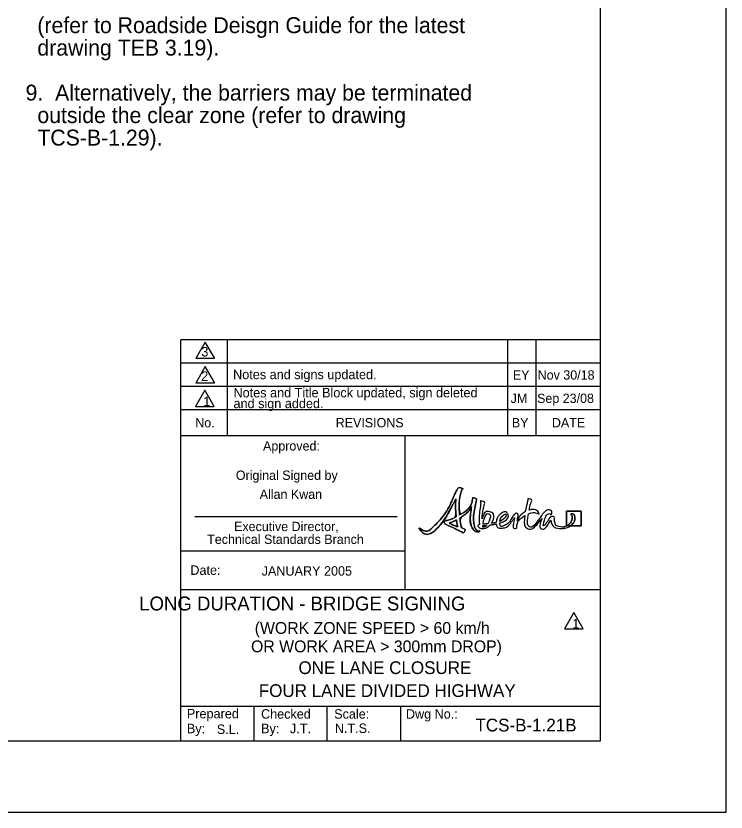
# Model space of a CAD drawing. Extents: x 2179 to 2395, y 134 to 413.
# Drawn here: x 2286.7 to 2394.7, y 133.8 to 254.8 of the extents above; entities that cross this region are included whole.
import ezdxf

# ---------------------------------------------------------------- set-up
doc = ezdxf.new("R2010")
doc.units = 0
for name, color, linetype in [('Level 1', 7, 'Continuous'), ('Level 2', 7, 'Continuous'), ('Level 20', 7, 'Continuous'), ('Level 22', 7, 'Continuous'), ('Level 44', 7, 'Continuous'), ('Level 53', 7, 'Continuous'), ('Level 60', 7, 'Continuous'), ('Level 7', 7, 'Continuous')]:
    doc.layers.add(name, color=color, linetype=linetype)

# ---------------------------------------------------------------- blocks, each defined once
blk = doc.blocks.new('REV1')
at = {"layer": 'Level 1'}
blk.add_lwpolyline([(0.114, 1.689), (-1.305, -0.781), (1.533, -0.781)], close=True, dxfattribs=at)
blk.add_text('1', height=1.448, rotation=360, dxfattribs=at).set_placement((-0.113, -0.724))

msp = doc.modelspace()

# ---------------------------------------------------------------- linework, layer by layer
at = {"layer": 'Level 1'}
for p, q in [((2375.65, 205.58), (2311.77, 205.58)), ((2375.65, 202.03), (2311.77, 202.03)), ((2375.65, 198.48), (2311.77, 198.48)), ((2375.65, 194.93), (2311.77, 194.93)), ((2311.78, 144.57), (2311.78, 191.03)), ((2311.78, 191.03), (2375.65, 191.03)), ((2345.83, 191.03), (2345.83, 167.62)), ((2311.78, 173.47), (2345.83, 173.47)), ((2311.78, 167.62), (2375.62, 167.62)), ((2311.78, 149.89), (2375.62, 149.89)), ((2322.91, 144.57), (2322.91, 149.89)), ((2334.04, 144.57), (2334.04, 149.89)), ((2345.17, 149.89), (2345.17, 144.57))]:
    msp.add_line(p, q, dxfattribs=at)
for points in [[(2394.75, 412.76), (2178.75, 412.76), (2178.75, 133.76), (2394.75, 133.76)], [(2375.62, 401.95), (2188.75, 401.95), (2188.75, 144.57), (2375.62, 144.57)], [(2315.4, 197.91), (2313.98, 195.44), (2316.82, 195.44)]]:
    msp.add_lwpolyline(points, close=True, dxfattribs=at)
at = {"layer": 'Level 2'}
msp.add_line((2345.85, 191.03), (2345.85, 191.03), dxfattribs=at)
at = {"layer": 'Level 20'}
for p, q in [((2311.78, 199.11), (2311.78, 205.58)), ((2318.87, 199.11), (2318.87, 205.58)), ((2361.46, 205.58), (2361.46, 191.03)), ((2365.77, 205.58), (2365.77, 191.03)), ((2311.78, 191.03), (2311.78, 199.11)), ((2318.87, 191.03), (2318.87, 199.11))]:
    msp.add_line(p, q, dxfattribs=at)
at = {"layer": 'Level 22'}
msp.add_line((2327.24, 144.57), (2327.24, 144.57), dxfattribs=at)
at = {"layer": 'Level 53'}
msp.add_line((2371.06, 177.31), (2370.51, 177.31), dxfattribs=at)
msp.add_lwpolyline([(2371.06, 177.31), (2372.67, 177.31), (2372.67, 179.54), (2370.44, 179.54), (2370.44, 177.31), (2370.51, 177.31)], dxfattribs=at)
for points, degree in [([(2357.07, 176.5), (2356.83, 176.53), (2356.52, 176.86), (2356.42, 177.4), (2356.25, 178.36), (2356.35, 179.32), (2356.64, 180.74), (2356.69, 181.01), (2356.87, 181.47), (2356.29, 181.56), (2356.1, 181.59), (2356.2, 181.5), (2356.15, 181.26), (2355.92, 180.2), (2355.06, 179.43), (2354.19, 178.92), (2354.1, 180.13), (2354.14, 181.48), (2354.36, 182.31), (2354.56, 183), (2354.79, 182.87), (2354.5, 183.02), (2354.2, 183.17), (2353.88, 182.97), (2353.62, 182.45), (2353.36, 181.93), (2352.17, 179.12), (2350.25, 177.22), (2349.28, 176.24), (2348.39, 176.74), (2348.21, 176.89), (2348.07, 177.02), (2348.02, 176.83), (2348.19, 176.64), (2348.99, 175.78), (2350.14, 176.27), (2350.56, 176.69), (2351.73, 177.86), (2353.08, 180.36), (2353.62, 181.42), (2353.57, 180.82), (2353.56, 179.82), (2353.67, 178.64), (2353.08, 178.36), (2352.55, 178.19), (2352.3, 178.12), (2352.02, 178.05), (2351.86, 177.94), (2351.85, 177.81), (2351.85, 177.68), (2352.03, 177.56), (2352.29, 177.43), (2352.76, 177.21), (2354.13, 176.56), (2354.47, 176.37), (2354.76, 176.2), (2354.9, 176.33), (2354.99, 176.51), (2355.1, 176.75), (2354.79, 176.88), (2354.49, 176.97), (2354.38, 177.37), (2354.29, 177.91), (2354.23, 178.5), (2354.92, 178.93), (2355.61, 179.5), (2356.01, 180.21), (2355.91, 179.62), (2355.65, 177.58), (2356.29, 176.73), (2356.43, 176.54), (2356.75, 176.33), (2357.05, 176.36), (2357.19, 176.37), (2357.27, 176.47), (2357.25, 176.5), (2357.24, 176.53), (2357.15, 176.49), (2357.07, 176.5)], 3), ([(2354.19, 178.92), (2354.1, 180.13), (2354.14, 181.48), (2354.36, 182.31), (2354.56, 183), (2354.79, 182.87), (2354.5, 183.02), (2354.2, 183.17), (2353.88, 182.97), (2353.62, 182.45), (2353.36, 181.93), (2352.17, 179.12), (2350.25, 177.22), (2349.28, 176.24), (2348.39, 176.74), (2348.21, 176.89), (2348.07, 177.02), (2348.02, 176.83), (2348.19, 176.64), (2348.99, 175.78), (2350.14, 176.27), (2350.56, 176.69), (2351.73, 177.86), (2353.08, 180.36), (2353.62, 181.42)], 3), ([(2353.62, 181.42), (2353.57, 180.82), (2353.56, 179.82), (2353.67, 178.64)], 2), ([(2357.07, 176.5), (2356.83, 176.53), (2356.52, 176.86), (2356.42, 177.4), (2356.25, 178.36), (2356.35, 179.32), (2356.64, 180.74), (2356.69, 181.01), (2356.87, 181.47), (2356.29, 181.56), (2356.1, 181.59), (2356.2, 181.5), (2356.15, 181.26), (2355.92, 180.2), (2355.06, 179.43), (2354.19, 178.92)], 3), ([(2357.61, 178.34), (2357.65, 178.91), (2357.74, 179.6), (2357.87, 180.24), (2357.93, 180.51), (2358.11, 180.98), (2357.53, 181.07), (2357.34, 181.1), (2357.37, 181.01), (2357.39, 180.76), (2357.41, 180.42), (2357.03, 178.38), (2357.23, 177.49)], 3), ([(2364.76, 179.68), (2364.83, 179.98), (2364.9, 180.28), (2364.98, 180.57), (2365.06, 180.84), (2365.28, 181.31), (2364.7, 181.4), (2364.52, 181.43), (2364.6, 181.34), (2364.54, 181.09), (2364.43, 180.63), (2364.29, 180.04), (2364.18, 179.45)], 3), ([(2354.23, 178.5), (2354.92, 178.93), (2355.61, 179.5), (2356.01, 180.21)], 2), ([(2356.01, 180.21), (2355.91, 179.62), (2355.65, 177.58), (2356.29, 176.73), (2356.43, 176.54), (2356.75, 176.33), (2357.05, 176.36), (2357.19, 176.37), (2357.27, 176.47), (2357.25, 176.5), (2357.24, 176.53), (2357.15, 176.49), (2357.07, 176.5)], 3), ([(2359.05, 177.68), (2359.46, 178.35), (2359.42, 179.26), (2358.82, 179.42), (2358.11, 179.59), (2357.76, 178.91), (2357.61, 178.34)], 3), ([(2360.27, 177.7), (2360.37, 177.73), (2360.45, 177.76), (2360.53, 177.79), (2361.41, 178.19), (2361.71, 178.78), (2361.49, 179.14), (2361.28, 179.48), (2360.67, 179.37), (2360.19, 178.87), (2359.95, 178.62), (2359.77, 178.19), (2359.75, 177.8)], 3), ([(2364.18, 179.45), (2363.71, 179.17), (2363.27, 178.72), (2362.95, 178.12)], 2), ([(2369.82, 177.11), (2368.9, 177.11), (2368.66, 177.82), (2368.62, 178.17), (2368.59, 178.41), (2368.64, 178.75), (2368.24, 178.7), (2367.95, 178.67), (2367.7, 178.12), (2367.34, 177.66), (2367.03, 177.26), (2366.89, 177.29), (2366.97, 177.64), (2367.05, 178.07), (2367.41, 179.07), (2367.82, 179.14), (2368.01, 179.18), (2368.08, 178.84), (2368.17, 179.05), (2368.25, 179.26), (2368.17, 179.71), (2367.75, 179.71), (2367.45, 179.71), (2367.1, 179.4), (2366.8, 179.04), (2366.55, 178.73), (2365.27, 176.84), (2364.73, 177.24), (2364.47, 177.43), (2364.5, 178.21), (2364.65, 179.13)], 3), ([(2364.65, 179.13), (2365.29, 179.37), (2365.83, 179.29), (2366.13, 179.15), (2366.27, 179.08), (2366.3, 179.09), (2366.23, 179.25), (2366.14, 179.49), (2365.62, 179.87), (2364.82, 179.7), (2364.8, 179.69), (2364.78, 179.69), (2364.76, 179.68)], 3), ([(2370.44, 179.54), (2370.44, 179.54), (2370.44, 177.31), (2370.44, 177.31), (2370.44, 177.31), (2370.51, 177.31), (2370.51, 177.31), (2370.99, 177.6), (2371.32, 178.15), (2371.31, 178.61), (2371.31, 179), (2371.11, 178.98), (2371.13, 179.04), (2371.2, 179.2), (2371.69, 179.11), (2371.72, 178.55), (2371.74, 178.08), (2371.5, 177.62), (2371.06, 177.31), (2371.06, 177.31), (2372.67, 177.31), (2372.67, 177.31), (2372.67, 177.31), (2372.67, 179.54), (2372.67, 179.54), (2372.67, 179.54), (2370.44, 179.54), (2370.44, 179.54)], 3), ([(2353.67, 178.64), (2353.08, 178.36), (2352.55, 178.19), (2352.3, 178.12), (2352.02, 178.05), (2351.86, 177.94), (2351.85, 177.81), (2351.85, 177.68), (2352.03, 177.56), (2352.29, 177.43), (2352.76, 177.21), (2354.13, 176.56), (2354.47, 176.37), (2354.76, 176.2), (2354.9, 176.33), (2354.99, 176.51), (2355.1, 176.75), (2354.79, 176.88), (2354.49, 176.97)], 3), ([(2352.6, 177.71), (2352.91, 177.82), (2353.3, 177.99), (2353.71, 178.21)], 2), ([(2352.6, 177.71), (2352.91, 177.82), (2353.3, 177.99), (2353.71, 178.21), (2353.77, 177.73), (2353.83, 177.39), (2353.9, 177.14), (2353.6, 177.25), (2353.16, 177.42), (2352.6, 177.71)], 3), ([(2353.71, 178.21), (2353.77, 177.73), (2353.83, 177.39), (2353.9, 177.14)], 2), ([(2354.49, 176.97), (2354.38, 177.37), (2354.29, 177.91), (2354.23, 178.5)], 2), ([(2357.76, 177.55), (2357.85, 178.27), (2358.23, 179.26), (2358.69, 179.1), (2358.96, 179.01), (2358.82, 178.17), (2358.47, 177.61)], 3), ([(2359.75, 177.58), (2359.8, 177.18), (2360.06, 176.88), (2360.65, 176.94), (2361.5, 177.02), (2362.25, 178.06), (2362.53, 178.56)], 3), ([(2362.95, 178.12), (2363, 178.39), (2363.09, 178.7), (2363.09, 178.91), (2363.1, 179.12), (2362.95, 179.17), (2362.89, 179.19), (2362.77, 179.22), (2362.62, 179.16), (2362.46, 178.95), (2362.11, 178.45), (2361.66, 177.66), (2360.98, 177.33), (2360.5, 177.1), (2360.28, 177.34), (2360.27, 177.7)], 3), ([(2360.74, 178.82), (2361.04, 179.1), (2361.19, 179.08), (2361.23, 179), (2361.31, 178.84), (2360.96, 178.28), (2360.29, 177.97)], 3), ([(2360.29, 177.97), (2360.35, 178.28), (2360.51, 178.61), (2360.74, 178.82)], 2), ([(2362.53, 178.56), (2362.48, 178.02), (2362.13, 176.85), (2362.73, 176.91), (2362.96, 176.93), (2362.86, 176.97), (2362.88, 177.17), (2362.93, 177.88), (2363.52, 178.48), (2364.1, 178.84)], 3), ([(2364.1, 178.84), (2364, 177.98), (2364.03, 177.21), (2364.42, 176.96), (2365.15, 176.51), (2366.17, 177.7), (2366.73, 178.42)], 3), ([(2366.73, 178.42), (2366.44, 177.78), (2366.28, 176.95), (2366.71, 176.83), (2367.22, 176.68), (2367.61, 177.52), (2368.08, 178.16)], 3), ([(2368.08, 178.16), (2368.13, 177.7), (2368.44, 176.9), (2369.68, 176.9), (2370.23, 176.9), (2370.71, 177.06), (2371.06, 177.31)], 3), ([(2370.51, 177.31), (2370.99, 177.6), (2371.32, 178.15), (2371.31, 178.61), (2371.31, 179), (2371.11, 178.98), (2371.13, 179.04), (2371.2, 179.2), (2371.69, 179.11), (2371.72, 178.55), (2371.74, 178.08), (2371.5, 177.62), (2371.06, 177.31)], 3), ([(2353.9, 177.14), (2353.6, 177.25), (2353.16, 177.42), (2352.6, 177.71)], 2), ([(2357.23, 177.49), (2356.98, 177.41), (2356.87, 177.22), (2357.2, 177.02), (2357.42, 176.88), (2357.91, 176.84), (2358.41, 177.08), (2358.58, 177.17), (2358.74, 177.29), (2358.86, 177.44)], 3), ([(2357.68, 177.12), (2357.71, 177.15), (2357.73, 177.19), (2357.73, 177.23), (2357.73, 177.26), (2357.74, 177.3), (2357.74, 177.33)], 3), ([(2357.88, 177.12), (2357.8, 177.11), (2357.74, 177.11), (2357.68, 177.12)], 2), ([(2357.74, 177.33), (2357.86, 177.33), (2358.06, 177.35), (2358.29, 177.37)], 2), ([(2358.47, 177.61), (2358.25, 177.59), (2358.01, 177.57), (2357.76, 177.55)], 2), ([(2358.29, 177.37), (2358.17, 177.24), (2358.03, 177.14), (2357.88, 177.12)], 2), ([(2358.86, 177.44), (2359.16, 177.47), (2359.47, 177.52), (2359.75, 177.58)], 2), ([(2359.75, 177.8), (2359.54, 177.75), (2359.31, 177.71), (2359.05, 177.68)], 2), ([(2370.51, 177.31), (2370.3, 177.19), (2370.07, 177.11), (2369.82, 177.11)], 2)]:
    msp.add_open_spline(points, degree=degree, dxfattribs=at)
at = {"layer": 'Level 60'}
for points in [[(2315.48, 205.25), (2314.08, 202.82)], [(2316.87, 202.82), (2315.48, 205.25)], [(2314.08, 202.82), (2314.06, 202.78), (2316.9, 202.78), (2316.87, 202.82)], [(2315.48, 201.53), (2314.08, 199.11)], [(2316.87, 199.11), (2315.48, 201.53)], [(2314.08, 199.11), (2314.06, 199.06), (2316.9, 199.06), (2316.87, 199.11)]]:
    msp.add_lwpolyline(points, dxfattribs=at)
at = {"layer": 'Level 7'}
msp.add_line((2313.89, 178.72), (2344.69, 178.72), dxfattribs=at)

# ---------------------------------------------------------------- block references
at = {"layer": 'Level 1'}
msp.add_blockref('REV1', (2371.45, 162.41), dxfattribs=at)

# ---------------------------------------------------------------- texts
for s, height, p in [('  (refer to Roadside Deisgn Guide for the latest', 2.419, (2288.12, 252.23)), ('  drawing TEB 3.19).', 2.419, (2288.12, 248.81)), ('9.  Alternatively, the barriers may be terminated', 2.419, (2288.12, 241.97)), ('  outside the clear zone (refer to drawing ', 2.419, (2288.12, 238.55)), ('  TCS-B-1.29).', 2.419, (2288.12, 235.13)), ('Original Signed by ', 1.4187, (2320.13, 184.28)), ('Allan Kwan', 1.419, (2323.76, 181.39)), ('S.L.', 1.433, (2317.23, 145.64))]:
    msp.add_text(s, height=height, dxfattribs=at).set_placement(p)
for s, height, p in [('Notes and Title Block updated, sign deleted ', 1.44, (2319.77, 196.83)), ('JM', 1.419, (2361.96, 195.98)), ('Sep 23/08', 1.419, (2365.98, 195.98)), ('1', 1.45, (2315.17, 195.5)), ('and sign added.', 1.44, (2319.77, 195.19)), ('No.', 1.419, (2313.95, 192.27)), ('REVISIONS', 1.419, (2335.33, 192.27)), ('BY', 1.419, (2362.14, 192.27)), ('DATE', 1.419, (2368.24, 192.27)), ('Date:', 1.433, (2313.21, 169.84)), ('Prepared', 1.44, (2312.67, 148.01)), ('Checked', 1.433, (2323.97, 147.97)), ('Scale:', 1.433, (2335.1, 147.97)), ('Dwg No.:', 1.433, (2346.02, 147.97)), ('By:', 1.44, (2312.67, 145.75)), ('By:   J.T.', 1.44, (2323.97, 145.75)), ('    N.T.S.   ', 1.4329, (2333.07, 145.79))]:
    msp.add_text(s, height=height, rotation=360, dxfattribs=at).set_placement(p)
at = {"layer": 'Level 44'}
for s, height, p in [('         LONG DURATION - BRIDGE SIGNING        ', 2.115, (2298.34, 164.42)), ('(WORK ZONE SPEED > 60 km/h', 1.8, (2323, 160.86)), ('OR WORK AREA > 300mm DROP)', 1.8, (2322.44, 158.06)), ('ONE LANE CLOSURE', 1.9352, (2329.66, 154.75)), ('FOUR LANE DIVIDED HIGHWAY', 1.935, (2323.62, 151.26))]:
    msp.add_text(s, height=height, dxfattribs=at).set_placement(p)
at = {"layer": 'Level 60'}
for s, height, p in [('3', 1.45, (2314.87, 203.05)), ('Notes and signs updated.', 1.44, (2319.71, 199.6)), ('Nov 30/18', 1.419, (2366.07, 199.53)), ('2', 1.45, (2314.85, 199.33)), ('EY', 1.419, (2362.29, 199.53))]:
    msp.add_text(s, height=height, rotation=360, dxfattribs=at).set_placement(p)
for s, height, p in [('JANUARY 2005', 1.434, (2324.06, 169.72)), ('TCS-B-1.21B', 1.935, (2356.6, 146.02))]:
    msp.add_text(s, height=height, dxfattribs=at).set_placement(p)
at = {"layer": 'Level 7'}
for s, height, p in [('Approved:', 1.419, (2324.27, 188.74)), ('Executive Director,', 1.4187, (2319.86, 176.49)), ('Technical Standards Branch', 1.4187, (2315.77, 174.54))]:
    msp.add_text(s, height=height, dxfattribs=at).set_placement(p)

doc.saveas('drawing.dxf')
